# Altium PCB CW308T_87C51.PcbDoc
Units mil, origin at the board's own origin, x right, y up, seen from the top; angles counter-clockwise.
Board outline 2200.03 x 3300.03 mil, 2 copper layers (Top Layer, Bottom Layer); 35 components, 66 nets, 282 pads, 47 vias.
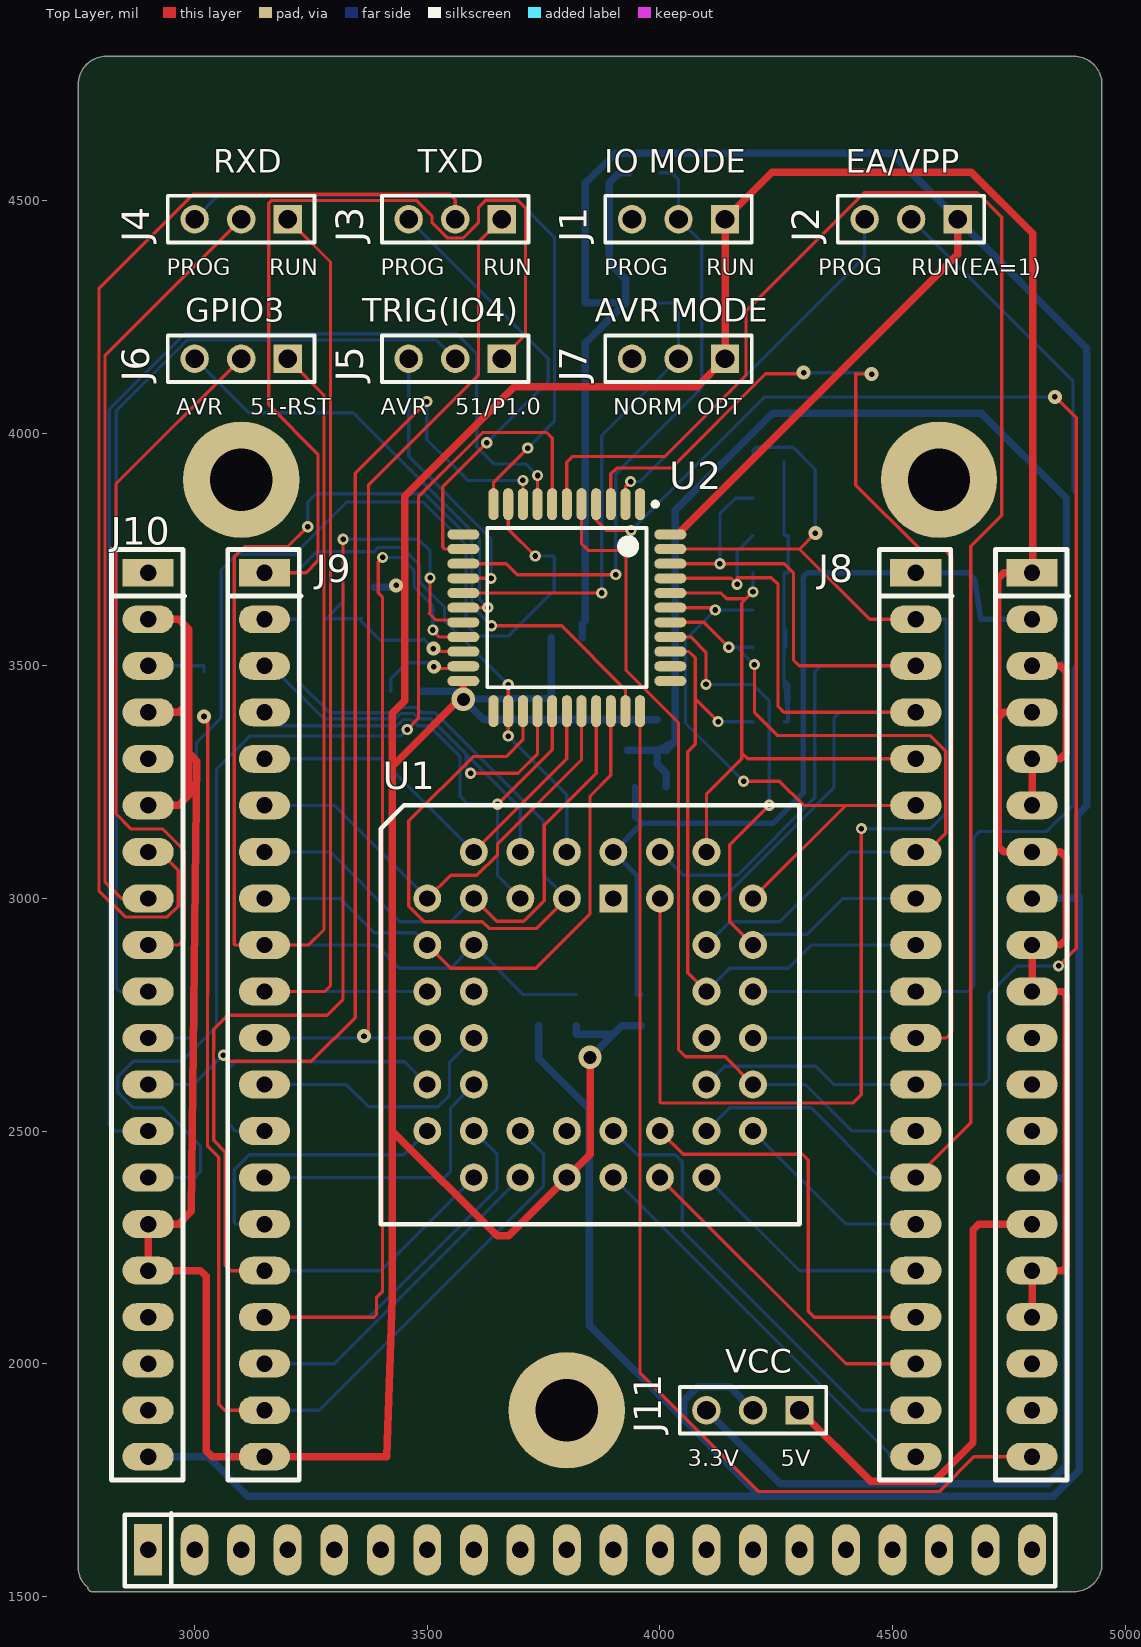
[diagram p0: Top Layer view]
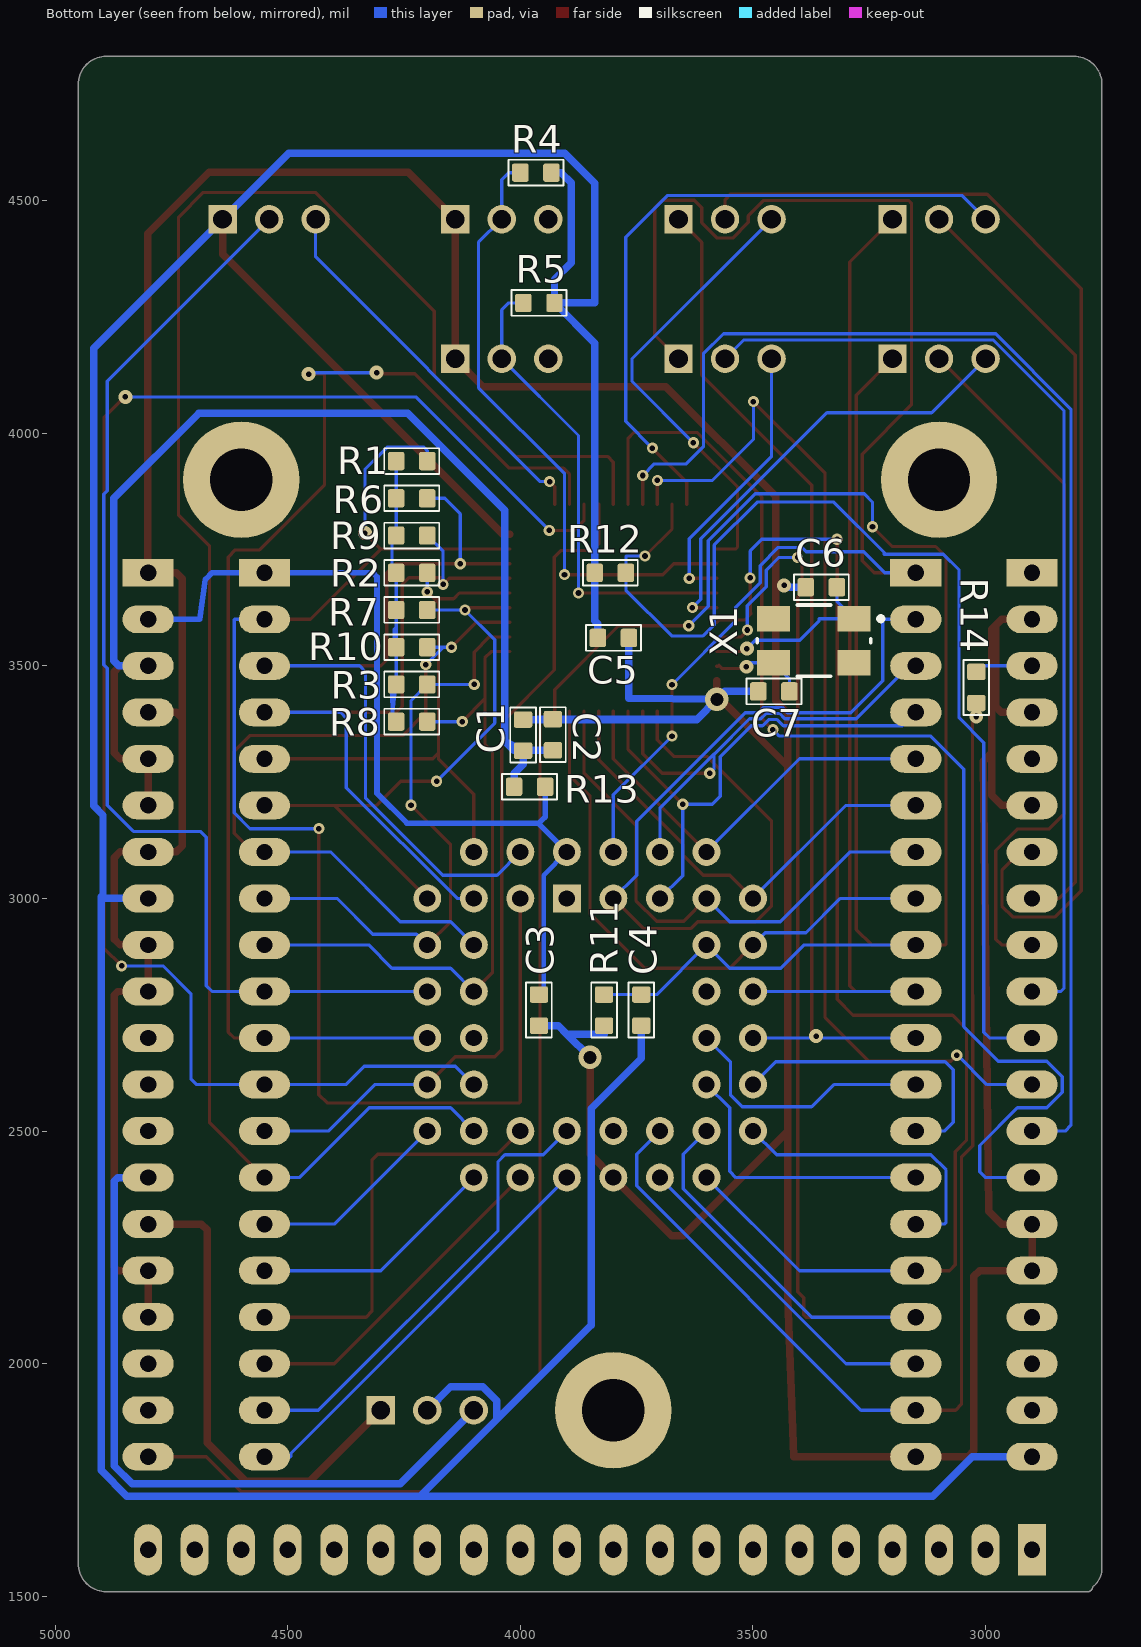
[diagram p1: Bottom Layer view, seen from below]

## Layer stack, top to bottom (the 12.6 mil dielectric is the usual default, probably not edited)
Top Solder: solder mask 0.4, Solder Resist, Dk 3.5
Top Layer: signal copper 1.4
Dielectric 1: dielectric 12.6, FR-4, Dk 4.8
Bottom Layer: signal copper 1.4
Bottom Solder: solder mask 0.4, Solder Resist, Dk 3.5

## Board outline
2769.99,1519.99 cw(c2800,1560) 2749.99,1560 2749.99,4750 cw(c2810,4750) 2810,4810.02 4890,4810.02 cw(c4890,4750) 4950.02,4750 4950.02,1570 cw(c4890,1570) 4890,1509.98 2780,1509.98 cw(c2780,1520)

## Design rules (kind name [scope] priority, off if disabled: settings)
BoardOutlineClearance [All] p1: gap=20 except(0: Arc-SplitContinuation Track-SplitContinuation SMDPad-SplitContinuation THPad-SplitContinuation Via-SplitContinuation Fill-SplitContinuation Poly-SplitContinuation Region-SplitContinuation Text-SplitContinuation)
Clearance Clearance_VCC [InNetClass('PWR')] p1: gap=10
Clearance Clearance_SENSITIVE [InNetClass('SENSITIVE')] p2: gap=15
Clearance Clearance_NORMAL [All] p3: gap=6
PolygonConnect [All] p1: connectstyle=Relief reliefconductorwidth=10 reliefentries=4 polygonreliefangle="90 Angle" airgapwidth=10
RoutingPriority RoutingPriority_SENSITIVE [InNetClass('SENSITIVE')] p1: routingpriority=10
RoutingPriority RoutingPriority_PWR [InNetClass('PWR')] p2: routingpriority=1
RoutingPriority RoutingPriority_ALL [All] p3: routingpriority=0
RoutingVias RoutingVias_PWR [InNetClass('PWR')] p1: holewidth=28 width=50 viastyle="Through Hole" minholewidth=26 minwidth=50 maxholewidth=28 maxwidth=50
RoutingVias [All] p2: holewidth=12 width=24 viastyle="Through Hole" minholewidth=12 minwidth=30 maxholewidth=28 maxwidth=50
SolderMaskExpansion [All] p1: expansion=4
Width Width_SENS [InNetClass('SENSITIVE')] p1: maxlimit=20 minlimit=10 preferedwidth=12 minimp=50.000000 maximp=50.000000 favimp=50.000000
Width WIDTH_PWR [InNetClass('PWR')] p2: maxlimit=100 minlimit=10 preferedwidth=16
Width [All] p3: maxlimit=100 minlimit=6 preferedwidth=7 minimp=50.000000 maximp=50.000000 favimp=50.000000
29 further rules are at their usual default settings.

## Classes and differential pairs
component class CW308T_87C51_CPU: C1 C2 C3 C4 C5 C6 C7 J1 J2 J3 J4 J5 J6 J7 J8 J9 R1 R2 R3 R4 R5 R6 R7 R8 R9 R10 R11 R12 R13 R14 U1 U2 X1
component class CW308T_87C51_CWCONN: J10 J11
net class SENSITIVE: SHUNTL
net class PWR: GND NetJ10_C14 NetJ10_C15 SHUNTH VCC
net class CLK: CLK NetJ9_19

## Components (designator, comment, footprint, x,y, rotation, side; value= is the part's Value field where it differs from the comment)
C1 "approved sub OK" CAPC1608X90N 3994,3351 r90 bottom
C2 "approved sub OK" CAPC1608X90N 3930,3352 r90 bottom
C3 "approved sub OK" CAPC1608X90N 3960,2760 r90 bottom
C4 "approved sub OK" CAPC1608X90N 3740,2760 r90 bottom
C5 "approved sub OK" CAPC1608X90N 3800,3560 r180 bottom
C6 "27p" CAPC1608X90N 3353,3669 r180 bottom
C7 "27p" CAPC1608X90N 3455,3445 r180 bottom
J1 "68000-203HLF" SMTC-TSW-103-07-X-S 4140,4460 r180 top
J2 "68000-203HLF" SMTC-TSW-103-07-X-S 4640,4460 r180 top
J3 "68000-203HLF" SMTC-TSW-103-07-X-S 3660,4460 r180 top
J4 "68000-203HLF" SMTC-TSW-103-07-X-S 3200,4460 r180 top
J5 "68000-203HLF" SMTC-TSW-103-07-X-S 3660,4160 r180 top
J6 "68000-203HLF" SMTC-TSW-103-07-X-S 3200,4160 r180 top
J7 "68000-203HLF" SMTC-TSW-103-07-X-S 4140,4160 r180 top
J8 "20-Pin Header" 801-87-020-10-001101 4550,3700 r0 top
J9 "20-Pin Header" 801-87-020-10-001101 3150,3700 r0 top
J10 "CW308_TARGETCON" CW308_TBOARD_CONN 2900,3700 r0 top locked
J11 "68000-203HLF" SMTC-TSW-103-07-X-S 4300,1900 r180 top
R1 "Thick Film" RESC1608X55N 4233.49,3940 r180 bottom
R2 "Thick Film" RESC1608X55N 4233.49,3700 r180 bottom
R3 "Thick Film" RESC1608X55N 4233.49,3460 r180 bottom
R4 "Thick Film" RESC1608X55N 3966.54,4560 r0 bottom
R5 "Thick Film" RESC1608X55N 3960,4280 r180 bottom
R6 "Thick Film" RESC1608X55N 4233.49,3860 r180 bottom
R7 "Thick Film" RESC1608X55N 4233.49,3620 r180 bottom
R8 "Thick Film" RESC1608X55N 4233.49,3380 r180 bottom
R9 "Thick Film" RESC1608X55N 4233.49,3780 r180 bottom
R10 "Thick Film" RESC1608X55N 4233.49,3540 r180 bottom
R11 "Thick Film" RESC1608X55N 3820,2760 r270 bottom
R12 "Thick Film" RESC1608X55N 3806.54,3700 r180 bottom
R13 "Thick Film" RESC1608X55N 3980,3240 r180 bottom
R14 "Thick Film" RESC1608X55N 3020,3453.46 r90 bottom
U1 "87C51" PLCC44_SOCKET 3500,3100 r0 top
U2 "ATmega8515-16AU" 44A_N 3800,3625 r270 top
X1 "ABMM2-8.000MHZ-E2-T" ABRA-ABMM2-4_V 3369,3554 r0 bottom

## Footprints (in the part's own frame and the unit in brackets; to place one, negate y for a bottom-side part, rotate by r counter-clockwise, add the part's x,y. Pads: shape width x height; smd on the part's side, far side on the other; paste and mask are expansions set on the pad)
44A_N [mm] "Thin QFP, 44-Leads, Body 10x10mm, Pitch 0.8mm, IPC Medium Density"
  oval 1.75x0.55 smd: 1(-5.65,4) 2(-5.65,3.2) 3(-5.65,2.4) 4(-5.65,1.6) 5(-5.65,0.8) 6(-5.65,0) 7(-5.65,-0.8) 8(-5.65,-1.6) 9(-5.65,-2.4) 10(-5.65,-3.2) 11(-5.65,-4) 23(5.65,-4) 24(5.65,-3.2) 25(5.65,-2.4) 26(5.65,-1.6) 27(5.65,-0.8) 28(5.65,0) 29(5.65,0.8) 30(5.65,1.6) 31(5.65,2.4) 32(5.65,3.2) 33(5.65,4)
  oval 0.55x1.75 smd: 12(-4,-5.65) 13(-3.2,-5.65) 14(-2.4,-5.65) 15(-1.6,-5.65) 16(-0.8,-5.65) 17(0,-5.65) 18(0.8,-5.65) 19(1.6,-5.65) 20(2.4,-5.65) 21(3.2,-5.65) 22(4,-5.65) 34(4,5.65) 35(3.2,5.65) 36(2.4,5.65) 37(1.6,5.65) 38(0.8,5.65) 39(0,5.65) 40(-0.8,5.65) 41(-1.6,5.65) 42(-2.4,5.65) 43(-3.2,5.65) 44(-4,5.65)
  silkscreen extent -5.77,-4.35 4.35,4.95, body extent -5,-5 5,5, height 1.2
801-87-020-10-001101 [mil]
  rect 110x60 hole 35: 1(0,0)
  oval 110x60 hole 35: 2(0,-100) 3(0,-200) 4(0,-300) 5(0,-400) 6(0,-500) 7(0,-600) 8(0,-700) 9(0,-800) 10(0,-900) 11(0,-1000) 12(0,-1100) 13(0,-1200) 14(0,-1300) 15(0,-1400) 16(0,-1500) 17(0,-1600) 18(0,-1700) 19(0,-1800) 20(0,-1900)
  silkscreen extent -79,-1950 79,50, body extent -50,-1950 50,50, height 224
ABRA-ABMM2-4_V [mm] "SMD, 4-Leads, Body 6.2x3.9mm, Pitch 4.4mm, Height 1.2mm"
  rect 1.8x1.4 smd: 1(-2.2,-1.2) 2(2.2,-1.2) 3(2.2,1.2) 4(-2.2,1.2)
  silkscreen extent -3.77,-1.95 3.1,1.95, body extent -3.1,-1.95 3.1,1.95, height 1.2
CAPC1608X90N [mm] "Chip Capacitor, Body 1.6x0.8mm, EIA 0603, IPC Medium Density"
  round 0.254 on Mech15: 0(0,0)
  rrect25% 0.9x1 smd: 1(-0.85,0) 2(0.85,0)
  Top Layer pour cut-out: -0.6,0.5 -0.4,0.7 0.4,0.7 0.6,0.5 0.6,-0.5 0.4,-0.7 -0.4,-0.7 -0.6,-0.5
  silkscreen extent -1.5,-0.7 1.5,0.7, body extent -0.85,-0.45 0.85,0.45, height 0.89
CW308_TBOARD_CONN [mil]
  rect 110x60 hole 35: A1(0,0) C1(1900,0)
  oval 110x60 hole 35: A2(0,-100) A3(0,-200) A4(0,-300) A5(0,-400) A6(0,-500) A7(0,-600) A8(0,-700) A9(0,-800) A10(0,-900) A11(0,-1000) A12(0,-1100) A13(0,-1200) A14(0,-1300) A15(0,-1400) A16(0,-1500) A17(0,-1600) A18(0,-1700) A19(0,-1800) A20(0,-1900) C2(1900,-100) C3(1900,-200) C4(1900,-300) C5(1900,-400) C6(1900,-500) C7(1900,-600) C8(1900,-700) C9(1900,-800) C10(1900,-900) C11(1900,-1000) C12(1900,-1100) C13(1900,-1200) C14(1900,-1300) C15(1900,-1400) C16(1900,-1500) C17(1900,-1600) C18(1900,-1700) C19(1900,-1800) C20(1900,-1900)
  rect 60x110 hole 35: B1(0,-2100)
  oval 60x110 hole 35: B2(100,-2100) B3(200,-2100) B4(300,-2100) B5(400,-2100) B6(500,-2100) B7(600,-2100) B8(700,-2100) B9(800,-2100) B10(900,-2100) B11(1000,-2100) B12(1100,-2100) B13(1200,-2100) B14(1300,-2100) B15(1400,-2100) B16(1500,-2100) B17(1600,-2100) B18(1700,-2100) B19(1800,-2100) B20(1900,-2100)
  round 250 hole 134: MH1(200,200) MH2(900,-1800) MH2(1700,200)
  silkscreen extent -79,-2179 1979,50, body extent -50,-2150 1950,50, height 224
PLCC44_SOCKET [mil]
  rect 60x60 hole 35: 1(400,-100)
  round 60 hole 35: 2(300,0) 3(300,-100) 4(200,0) 5(200,-100) 6(100,0) 7(0,-100) 8(100,-100) 9(0,-200) 10(100,-200) 11(0,-300) 12(100,-300) 13(0,-400) 14(100,-400) 15(0,-500) 16(100,-500) 17(0,-600) 18(100,-700) 19(100,-600) 20(200,-700) 21(200,-600) 22(300,-700) 23(300,-600) 24(400,-700) 25(400,-600) 26(500,-700) 27(500,-600) 28(600,-700) 29(700,-600) 30(600,-600) 31(700,-500) 32(600,-500) 33(700,-400) 34(600,-400) 35(700,-300) 36(600,-300) 37(700,-200) 38(600,-200) 39(700,-100) 40(600,0) 41(600,-100) 42(500,0) 43(500,-100) 44(400,0)
  silkscreen extent -100,-800 800,100, body extent -92,-792 792,92, height 302
RESC1608X55N [mm] "Chip Resistor, Body 1.6x0.8mm, EIA 0603, IPC Medium Density"
  round 0.254 on Mech15: 0(0,0)
  rrect25% 0.9x1 smd: 1(-0.85,0) 2(0.85,0)
  Top Layer pour cut-out: -0.6,0.5 -0.4,0.7 0.4,0.7 0.6,0.5 0.6,-0.5 0.4,-0.7 -0.4,-0.7 -0.6,-0.5
  silkscreen extent -1.5,-0.7 1.5,0.7, body extent -0.87,-0.47 0.88,0.48, height 0.54
SMTC-TSW-103-07-X-S [mm] ".025 SQ Post Terminal Strip Assembly, 1x3 Pins, Vertical, 2.54mm Pitch, Male"
  rect 1.55x1.55 hole 1.02: 1(0,0)
  round 1.55 hole 1.02: 2(2.54,0) 3(5.08,0)
  silkscreen extent -1.46,-1.27 6.54,1.27, body extent -1.27,-1.27 6.35,1.27, height 8.38

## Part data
C1 C2 C3 C4 C5: library part CAPC_100n_0603_X7R_50V_10%, "Capacitor SMD Cer 100nF 10% 50V X7R 0603"
C6 C7: library part CAPC_27p_0603_NP0_100V_1%, "Capacitor SMD Cer 27pF 1% 100V NP0 0603"
J1 J2 J3 J4 J5 J6 J7 J11: library part CMP-1024-00333-1
J8 J9: library part 801-87-020-10-001101, "1x20 Header, Machined"
J10: library part CW308_TBOARD, "CW308 \"Standard\" Target Board Connector"
R1 R2 R3 R4 R5 R6 R7 R8 R9 R10 R11 R12: library part RES_10K_0603_1%, "Resistor SMD chip 10k Ohm 0.1W 1% 0603"
R13 R14: library part RES_51R_0603_1%, "Resistor SMD chip 51 Ohm 0.1W 1% 0603"
U2: library part CMP-0095-00300-2, "8-bit AVR Microcontroller, 8KB Flash, 512 Bytes EEPROM, 512 Bytes SRAM, 4.5-5.5V, 44-pin TQFP, Industrial Grade (-40°C to 85°C)"
X1: library part CMP-0277-00003-1, "Ceramic Surface Mount Low Profile Quartz Crystal, 8 MHz, -20 to 70 degC, 4-Pin 6 x 3.6 x 1.2 mm SMD, RoHS, 1000pcs / Reel"

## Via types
v1: diameter 24, hole 12, Top Layer to Bottom Layer, tented both sides, 36 vias
v2: diameter 30, hole 12, Top Layer to Bottom Layer, tented both sides, 9 vias
v3: diameter 50, hole 28, Top Layer to Bottom Layer, 2 vias

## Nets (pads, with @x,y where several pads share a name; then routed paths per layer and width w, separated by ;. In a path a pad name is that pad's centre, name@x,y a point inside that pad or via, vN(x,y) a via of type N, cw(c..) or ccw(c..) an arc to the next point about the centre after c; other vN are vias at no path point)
51_RESET: C4.2 J6.1 J9.9 R11.1 U1.10 U2.32 | length 4286.4
  Top Layer w7: J6.1 3278,4082 3278,2933 3245,2900 J9.9 3086.5,2900 3085.09,2901.41 3085.09,3734.09 3107.5,3756.5 3200.5,3756.5 v1(3243,3799) ; v1(3638,3586) 3789,3586 3925.98,3449.02 U2.32
  Bottom Layer w7: J9.9 3390,2900 3440,2850 3550,2850 U1.10 3706.54,2793.46 C4.2 R11.1 ; v1(3243,3799) 3243,3852 3261,3870 3495,3870 3596.25,3768.75 3596.25,3627.75 v1(3638,3586)
51_RX: J4.1 J9.10 U1.11 | length 2182.8
  Top Layer w7: J9.10 3279.5,2800 3292,2812.5 3292,4368 J4.1
  Bottom Layer w7: J9.10 U1.11
51_TX: J3.1 J9.11 U1.13 | length 2228.6
  Top Layer w7: v2(3364,2704) 3373.5,2713.5 3373.5,3888.5 3610,4125 3610,4410 J3.1
  Bottom Layer w7: J9.11 U1.13
ALE/PROG: J8.11 U1.33 U2.3 | length 2715.7
  Top Layer w7: U2.3 3894.49,3912.5 3906.99,3925 4024.01,3925 4227.01,4127.99 4306.99,4127.99 v2(4309,4130) ; v2(4455,4127) 4422,4127 4421,4128 4421,3888.5 4560.5,3749 4612.5,3749 4627.73,3733.77 4627.73,2712.73 4615,2700 J8.11
  Bottom Layer w7: U1.33 J8.11 ; v2(4309,4130) 4452,4130 v2(4455,4127)
AVR_EA: J2.3 U2.2 | length 837.2
  Top Layer w7: U2.2 3925.98,3884.98 v1(3937,3896)
  Bottom Layer w7: v1(3937,3896) 3957,3896 4440,4379 J2.3
AVR_GPIO3: J6.3 U2.17 | length 980.4
  Top Layer w7: U2.17 v1(3630.13,3625)
  Bottom Layer w7: J6.3 3116,4044 3341,4044 3612,3773 3612,3643.13 v1(3630.13,3625)
AVR_MODE1: J1.2 R4.2 U2.14 | length 1329.7
  Top Layer w7: U2.14 3670,3719.49 3693.49,3696 v1(3905,3696)
  Bottom Layer w7: v1(3905,3696) 3905,3913 4090,4098 4090,4410 J1.2 4040,4545 4025,4560 R4.2
AVR_MODE2: J7.2 R5.1 U2.16 | length 1027
  Top Layer w7: U2.16 v1(3875,3656.5)
  Bottom Layer w7: v1(3875,3656.5) 3875,3995 J7.2 4040,4265 4025,4280 R5.1
AVR_RST: J10.A11 R12.2 U2.10 | length 2413.2
  Top Layer w7: U2.10 3674.02,3794 v1(3732,3736.02)
  Bottom Layer w7: J10.A11 2991.5,2700 3004,2712.5 3004,3335 3057,3388 3057,3706 3090.65,3739.65 3218,3739.65 3218,3743.59 3326.41,3852 3491,3852 3583.25,3759.75 3583.25,3588.25 3607.2,3564.3 3674.91,3564.3 3773.07,3662.47 R12.2 3773.07,3735 3772.05,3736.02 v1(3732,3736.02)
AVR_RX: J4.3 U2.11 | length 1459.6
  Top Layer w7: U2.11 3642.52,3894.52 v1(3716,3968)
  Bottom Layer w7: J4.3 3051,4511 3683.55,4511 3773.28,4421.28 3773.28,4025.28 v1(3716,3968)
AVR_TRIG: J5.3 U2.15 | length 604.8
  Top Layer w7: U2.15 v1(3637,3687.99)
  Bottom Layer w7: J5.3 3460,3950 3637,3773 v1(3637,3687.99)
AVR_TX: J3.3 U2.13 | length 969
  Top Layer w7: U2.13 3537.5,3750.98 3533.26,3755.23 3533.26,3884.88 v1(3628,3979.63)
  Bottom Layer w7: J3.3 3760,4160 3760,4111.63 v1(3628,3979.63)
CLK: J10.A3 R14.2 | length 133.1
  Bottom Layer w7: J10.A3 3020,3500 R14.2
EA/VPP: J2.2 J8.10 U1.35 | length 2450.6
  Bottom Layer w7: U1.35 J8.10 4662.5,2800 4675,2812.5 4675,3131.5 4687.5,3144 4831.5,3144 4888,3200.5 4888,3494.59 4895.5,3502.09 4895.5,3868.91 4888,3876.41 4888,3995.59 4888,4112 J2.2
GND: C1.2 C2.2 C3.1 C5.2 C6.1 C7.1 J1.1 J7.1 J9.20 J10.A2 J10.A4 J10.A6 J10.A15 J10.A16 J10.C1 J10.C4 J10.C7 J10.C9 J10.C10 J10.C16 J10.C17 R11.2 U1.22 U2.22 | length 12493.2
  Top Layer w16: J10.A6 2965.5,3200 2986.99,3221.49 2986.99,3313.01 ; J10.A4 2966,3400 2978.5,3412.5 2978.5,3587 ; J10.A2 2965.5,3600 2978.5,3587 ; v3(3577.56,3428) v3@3577.56,3436.56 ; U2.22 v3@3577.56,3436.56 ; v3(3850,2658.54) 3850,2450 U1.22 3675,2275 3650,2275 3425,2500 ; 4726.72,3112.78 4726.72,3687.5 4739.22,3700 J10.C1 4801,3700 4801,4429.14 4669.14,4561 4241,4561 J1.1 J7.1 4080.15,4100.15 3687.15,4100.15 3451.17,3864.17 3451.17,3424.63 3425,3398.46 3425,3292 ; J10.C17 J10.C16 4865.5,2200 4873.28,2207.78 4873.28,2792.22 4865.5,2800 J10.C10 J10.C9 4860.5,2900 4873.23,2912.73 4873.23,3087.27 4860.5,3100 J10.C7 4739.5,3100 4726.77,3112.73 4726.77,3387.27 4739.5,3400 J10.C4 ; 2978.5,3587 2986.99,3578.51 2986.99,3313.01 ; 2986.99,3313.01 3004.95,3295.05 2992.79,2327.29 2965.5,2300 J10.A15 J10.A16 3012.5,2200 3025,2187.5 3025,1812.5 3037.5,1800 J9.20 3412.5,1800 3425,2141.11 3425,2500 ; 3425,2500 3425,3292 ; 3425,3292 3428,3289 3430,3289 v3@3577.56,3436.56
  Bottom Layer w16: C6.1 3429,3669 v2(3433,3673) ; C7.1 3560.56,3445 v3@3576.97,3428.59 ; C5.2 3766.54,3430 3577.56,3428.6 v3@3576.97,3428.59 ; R11.2 3820,2708.5 3899.96,2708.5 ; v3(3850,2658.54) 3899.96,2708.5 ; C3.1 3918,2726.54 3899.96,2708.5 ; v3@3576.97,3428.59 v3(3577.56,3428) 3620.1,3385.46 ; 3620.1,3385.46 C2.2 ; 3620.1,3385.46 3621.1,3384.46 C2.2@3930,3384.46 ; C2.2@3930,3384.46 C2.2 ; C2.2@3930,3384.46 C1.2 3961,3385.46 C2.2
GPIO3: J6.2 J10.A9 | length 1542.8
  Top Layer w7: J10.A9 2965.5,2900 2978,2912.5 2978,3103 2932,3149 2863.98,3149 2830.99,3181.99 2830.99,3890.99 J6.2
GPIO4: J5.2 J10.A10 | length 2120.8
  Bottom Layer w7: J10.A10 2838.5,2800 2831.43,2807.07 2831.43,4048.04 2983.69,4200.31 3519.69,4200.31 J5.2
LED1: J10.C18
LED2: J10.C19
LED3: J10.C20 U2.33 | length 2401.8
  Top Layer w7: U2.33 3957.48,1979.88 4212.31,1725.05 4600.05,1725.05 4675,1800 J10.C20
MISO: J10.A13 U2.8 | length 2920.5
  Top Layer w7: U2.8 v1(3737.01,3909)
  Bottom Layer w7: J10.A13 2829,2500 2816.5,2512.5 2816.5,4051.85 2978.33,4213.68 3563.33,4213.68 3606.46,4170.54 3606.46,3970.54 3643.01,3934 3712.01,3934 v1(3737.01,3909)
MOSI: J10.A14 U2.7 | length 2689.4
  Top Layer w7: v1(3457,3363) 3481,3387 3481,3863.03 3619.48,4001.52 3756.48,4001.52 3768.5,3989.5 U2.7
  Bottom Layer w7: J10.A14 3000,2400 3012.5,2412.5 3012.5,2468.95 2931.45,2550 2868.45,2550 2834.97,2583.47 2834.97,2616.47 2868.5,2650 2972.5,2650 3047,2724.5 3047,3278 3118,3349 3443,3349 v1(3457,3363)
NetC6_2: C6.2 U2.20 X1.1 | length 412.5
  Top Layer w7: v2(3513,3537) 3519.49,3530.51 U2.20
  Bottom Layer w7: C6.2 3319.54,3638.39 X1.1 3358.24,3601.24 3358.24,3595.76 3399,3555 3488,3555 3490,3557 3493,3557 v2(3513,3537)
NetC7_2: C7.2 U2.21 X1.3 | length 206.8
  Top Layer w7: v2(3514,3498) 3518,3494 3566,3494 3573,3501 3574.98,3499.02 U2.21
  Bottom Layer w7: C7.2 3421.54,3472.68 X1.3 3505.24,3506.76 v2(3514,3498)
NetJ8_15: J8.15 U1.29 | length 432.8
  Bottom Layer w7: U1.29 4400,2300 J8.15
NetJ8_16: J8.16 U1.28 | length 532.8
  Bottom Layer w7: U1.28 4300,2200 J8.16
NetJ9_12: J9.12 U1.14 | length 572.8
  Bottom Layer w7: J9.12 3326,2600 3374,2552 3523,2552 3548,2577 3548,2648 U1.14
NetJ9_13: J9.13 U1.15 | length 658.7
  Bottom Layer w7: J9.13 3088.5,2500 3069.75,2518.75 3069.75,2631.75 3087,2649 3451,2649 U1.15
NetJ9_14: J9.14 U1.16 | length 612.8
  Bottom Layer w7: J9.14 3536.5,2400 3550,2413.5 3550,2550 U1.16
NetJ9_15: J9.15 U1.17 | length 629.1
  Bottom Layer w7: J9.15 3088.5,2300 3084.96,2303.54 3084.96,2416.53 3117.43,2449 3449,2449 U1.17
NetJ9_18: J9.18 U1.20 | length 715.7
  Bottom Layer w7: J9.18 3300,2000 U1.20
NetJ9_19: J9.19 R14.1 U1.21 | length 2533.7
  Top Layer w7: v2(3020,3391) 3028,3383 3028,2793 3027.5,2792.5 3027.5,2468.5 3052,2444 3052,1912.5 3064.5,1900 J9.19
  Bottom Layer w7: J9.19 3268,1900 3750,2382 3750,2450 U1.21
NetJ10_C14: J10.C14 J11.3 | length 1543.4
  Bottom Layer w16: J11.3 4258.5,1741.5 4834.5,1741.5 4873.28,1780.28 4873.28,2392.22 4865.5,2400 J10.C14
NetJ10_C15: J10.C15 J11.1 | length 1060.4
  Top Layer w16: J11.1 4453,1747 4590,1747 4673,1830 4673,2287.5 4685.5,2300 J10.C15
NetR1_1: R1.1 R2.1 R3.1 R6.1 R7.1 R8.1 R9.1 R10.1 | length 828.1
  Bottom Layer w7: R8.1 R8.1@4276,3380 ; R3.1 R3.1@4266.95,3469.05 ; R1.1 R6.1 R9.1 4276,3780 4276,3700 R2.1 R7.1 4266.95,3583.05 ; R3.1@4266.95,3469.05 R8.1@4276,3380 ; R3.1@4266.95,3469.05 R10.1 ; R3.1@4266.95,3469.05 4277,3459 R8.1@4276,3380 ; R3.1@4266.95,3469.05 4267.86,3460.09 4275.91,3380.91 R8.1@4276,3380 ; R10.1 4271,3540 4271,3579 4266.95,3583.05 ; R10.1 4266.95,3583.05
P2.6: J8.14 U1.30 U2.6 | length 4041.6
  Top Layer w7: U2.6 3800,3937.5 3812.5,3950 4011,3950 4185,4124 4185,4262 4440.59,4517.59 4681.58,4517.59 4734.62,4464.55 4734.62,3823.62 4668,3757 4668,2518 J8.14
  Bottom Layer w7: U1.30 4150,2550 4325,2550 4475,2400 J8.14
P2.7: J8.13 U1.31 U2.5 | length 1880.2
  Top Layer w7: U2.5 3831.5,3762.5 3846,3748 3912.5,3748 3927,3733.5 3927,3491 4040,3378 4040,2675 4055,2660 4140,2660 U1.31
  Bottom Layer w7: U1.31 4313,2600 4413,2500 J8.13
P3.6: J9.16 U1.18 U2.18 | length 2847.5
  Top Layer w7: J9.16 3077.5,2200 3065,2212.5 3065,2456 3041,2480 3041,2653.59 3040.5,2654.09 3040.5,2671.91 3041,2672.41 3041,2719 3071,2749 3285,2749 3319,2783 v1(3319,3772) ; v1(3506,3689) 3506,3614.5 3504,3612.5 3518,3598.5 3572.56,3598.5 U2.18
  Bottom Layer w7: J9.16 3400,2200 U1.18 ; v1(3319,3772) 3481,3772 3506,3747 v1(3506,3689)
P3.7: J9.17 U1.19 U2.19 | length 2939.8
  Top Layer w7: J9.17 3385.5,2100 3390.71,2105.21 3390.71,2141.91 3403.5,2154.7 3403.5,3648.05 3394.5,3657.05 3394.5,3723.5 v1(3404,3733) ; v1(3512,3577) 3512,3575.01 3525,3562.01 U2.19
  Bottom Layer w7: J9.17 3374,2100 3650,2376 3650,2450 U1.19 ; v1(3404,3733) 3444,3733 3471.5,3705.5 3471.5,3669.5 3512,3629 v1(3512,3577)
PA0: J5.1 J9.1 U1.2 U2.24 | length 3057.5
  Top Layer w7: J9.1 3239.5,3700 3264.92,3725.42 3264.92,3955.08 3159.31,4060.69 3159.31,4493.96 3165.67,4500.33 3476.67,4500.33 3510,4467 3510,4453 3543.55,4419.45 3576.77,4419.45 3610,4452.69 3610,4484.69 3625.75,4500.43 3694.74,4500.43 3711,4484.18 3711,4211 J5.1 ; v1(3674.02,3348.98) U2.24 v1(3674.02,3459.59)
  Bottom Layer w7: J9.1 3217,3700 3262,3745 3385.59,3745 3395.09,3754.5 3445.5,3754.5 3484.5,3715.5 3484.5,3678.5 3537,3626 3537,3596.6 v1(3674.02,3459.59) ; v1(3674.02,3348.98) 3800,3223 U1.2
PA1: J9.2 U1.3 U2.25 | length 2001.9
  Top Layer w7: U2.25 3705.51,3341.13 3669.38,3305 3598.38,3305 3460.36,3166.97 3460.36,2983.23 3493.59,2950 3618.59,2950 3633.09,2935.5 3735.5,2935.5 U1.3
  Bottom Layer w7: J9.2 3221,3600 3221,3468 3290,3399 3425.83,3399 3437.33,3410.5 3476.67,3410.5 3488.17,3399 3517,3399 3750,3166 3750,3050 U1.3
PA2: J9.3 U1.4 U2.26 | length 1077.6
  Top Layer w7: v1(3593,3269) 3694.98,3269 3737.01,3311.03 U2.26
  Bottom Layer w7: J9.3 3164,3500 3278,3386 3431.21,3386 3442.71,3397.5 3471.29,3397.5 3482.79,3386 3507.47,3386 3583.5,3309.97 3583.5,3278.5 v1(3593,3269) ; 3584,3310 3700,3194 U1.4
PA3: J9.4 U1.5 U2.27 | length 1115.4
  Top Layer w7: v1(3651,3202.5) 3768.5,3320 U2.27
  Bottom Layer w7: J9.4 3179,3371 3434.59,3371 3448.09,3384.5 3465.91,3384.5 3479.41,3371 3504.08,3371 3570.5,3304.58 3570.5,3219.5 3587.5,3202.5 v1(3651,3202.5) 3651,3049 U1.5
PA4: J9.5 U1.6 U2.28 | length 918.2
  Top Layer w7: U1.6 3800,3300 U2.28
  Bottom Layer w7: J9.5 3400,3300 U1.6
PA5: J9.6 U1.7 U2.29 | length 1005.9
  Top Layer w7: U1.7 3550,3050 3606.74,3050 3651,3094.26 3651,3117.26 3831.5,3297.76 U2.29
  Bottom Layer w7: J9.6 3300,3200 U1.7
PA6: J9.7 U1.8 U2.30 | length 1176.3
  Top Layer w7: U1.8 3649,2951 3707,2951 3751.5,2995.5 3751.5,3157.57 3862.99,3269.06 U2.30
  Bottom Layer w7: J9.7 3291,3100 3441,2950 3550,2950 U1.8
PA7: J9.8 U1.9 U2.31 | length 1264.6
  Top Layer w7: U1.9 3550,2850 3733,2850 3850,2967 3850,3220.18 3894.49,3264.66 U2.31
  Bottom Layer w7: J9.8 3312,3000 3386,2926 3474,2926 U1.9
PA8: J8.20 U1.24 | length 902
  Bottom Layer w7: U1.24 4493,1807 4493,1801 4494,1800 J8.20
PA9: J8.19 U1.25 | length 985.2
  Bottom Layer w7: U1.25 3951,2449 4033,2449 4048,2434 4048,2286 4434,1900 J8.19
PA10: J8.18 U1.26 | length 715.7
  Top Layer w7: U1.26 4400,2000 J8.18
PA11: J8.17 U1.27 | length 906.1
  Top Layer w7: U1.27 4050,2450 4306.5,2450 4319,2437.5 4319,2112.5 4331.5,2100 J8.17
PD0: J8.2 R1.2 U1.43 U2.43 | length 3081.4
  Top Layer w7: U1.43 4000,2562.5 4002.12,2560.38 4415.12,2560.38 4433,2578.26 v1(4433,3150) ; U2.43 4300,3750.98 ; v2(4334,3785) 4300,3750.98 ; J8.2 4450.98,3600 4300,3750.98
  Bottom Layer w7: R1.2 4200.02,3962.5 4207.09,3969.57 4286.43,3969.57 4334,3922 v2(4334,3785) ; v1(4433,3150) 4581,3150 4615.04,3184.04 4615.04,3598.96 4614,3600 J8.2
PD1: J8.3 R6.2 U1.42 U2.42 | length 1836.4
  Top Layer w7: U2.42 v1(4129,3719.49) 4267.51,3719.49 4287,3700 4287,3512.5 4299.5,3500 J8.3
  Bottom Layer w7: U1.42 4050,3050 4167,3050 4333,3216 4333,3487.5 4345.5,3500 J8.3 ; v1(4129,3719.49) 4129,3826.5 4162.5,3860 R6.2
PD2: J8.4 R9.2 U1.41 U2.41 | length 1643.5
  Top Layer w7: U2.41 4153.01,3687.99 v1(4166,3675) 4166,3689.5 4239.5,3689.5 4254,3675 4254,3412.5 4266.5,3400 J8.4
  Bottom Layer w7: U1.41 4136,3000 4374,3238 4374,3387.5 4386.5,3400 J8.4 ; v1(4166,3675) 4166,3745.98 R9.2
PD3: J8.5 R2.2 U1.40 U2.40 | length 1222.3
  Top Layer w7: U2.40 4130.9,3656.5 4143.4,3644 4185.02,3644 ; U1.40 4100,3224 4176,3300 4176,3312.5 ; J8.5 4188.5,3300 4176,3312.5 ; 4176,3312.5 4176,3634.98 ; 4176,3634.98 v1(4200.02,3659) 4185.02,3644 ; 4176,3634.98 4185.02,3644
  Bottom Layer w7: v1(4200.02,3659) R2.2
PD4: J8.6 R7.2 U1.39 U2.39 | length 1541.3
  Top Layer w7: U2.39 4114,3625 v1(4119,3620) ; v1(4180,3252) 4257,3252 4309,3200 ; U1.39 4400,3200 ; 4309,3200 J8.6 4400,3200 ; 4309,3200 4400,3200
  Bottom Layer w7: v1(4180,3252) 4055,3377 4055,3556 v1(4119,3620) R7.2
PD5: J8.7 R10.2 U1.38 U2.38 | length 1592.3
  Top Layer w7: U2.38 4094.5,3593.5 v1(4148,3540) ; v1(4203.23,3502.5) 4203.23,3399.77 4253,3350 4581.31,3350 4614.66,3316.66 4614.66,3139.66 4575,3100 J8.7
  Bottom Layer w7: U1.38 4150,2950 4258,2950 4408,3100 J8.7 ; v1(4148,3540) 4165.73,3540 ; R10.2 4165.73,3540 ; v1(4203.23,3502.5) 4165.73,3540
PD6: J8.8 R3.2 U1.37 U2.37 | length 1282.4
  Top Layer w7: U2.37 4066.5,3562.01 4099,3529.51 v1(4099,3460) ; U1.37 4150,2950 4150,3115.27 v1(4235,3200.27)
  Bottom Layer w7: v1(4099,3460) R3.2 4235,3425.02 v1(4235,3200.27) ; U1.37 4223,2923 4317,2923 4394,3000 J8.8
PD7: J8.9 R8.2 U1.36 U2.36 | length 1435.1
  Top Layer w7: U2.36 4062.5,3530.51 4076,3517.01 4076,3429 ; U1.36 4060,2840 4060,3315 4076,3331 4076,3429 ; v1(4125,3380) 4076,3429
  Bottom Layer w7: U1.36 4150,2850 4276,2850 4326,2900 J8.9 ; v1(4125,3380) R8.2
PSEN: J8.12 U1.32 U2.4 | length 3409.4
  Top Layer w7: U2.4 3862.99,3812.5 3884.49,3791 v1(3938,3791) ; v2(4849,4078) 4850,4078 4895,4033 4895,2893 v1(4857,2855)
  Bottom Layer w7: v1(3938,3791) 4225,4078 v2(4849,4078) ; U1.32 4139.55,2639.55 4335.45,2639.55 4375,2600 J8.12 4695.5,2600 4708,2612.5 4708,2795 4768,2855 v1(4857,2855)
RX: J4.2 J10.A8 | length 1653.4
  Top Layer w7: J10.A8 2842,3000 2807.5,3034.5 2807.5,4167.5 J4.2
SCK: J10.A12 U2.9 | length 2278.8
  Top Layer w7: v1(3062,2663) 3075,2650 3251,2650 3345,2744 3345,3914 v1(3499,4068) ; U2.9 v1(3705.51,3898.51)
  Bottom Layer w7: J10.A12 2997,2600 3060,2663 v1(3062,2663) ; v1(3499,4068) 3499,3986.46 3586.95,3898.51 v1(3705.51,3898.51)
SHUNTH: C1.1 C2.1 J10.C3 J10.C5 J10.C6 R13.1 | length 2600.7
  Top Layer w16: J10.C6 J10.C5 4860.5,3300 4873.23,3312.73 4873.23,3487.27 4860.5,3500 J10.C3
  Bottom Layer w16: C2.1 C1.1@3994,3318.54 ; R13.1 4013.46,3269 3994,3288.46 C1.1 ; J10.C3 4863,3500 4874,3511 4874,3860 4690.75,4043.25 4242.06,4043.25 4033.24,3834.43 4033.24,3337.5 ; C1.1 3995.97,3318.54 4014.28,3318.54 4033.24,3337.5 ; C1.1 C1.1@3994,3318.54 ; C1.1@3994,3318.54 4033.24,3337.5
SHUNTL: C3.2 J8.1 J10.C2 R13.2 U1.44 | length 1923.9
  Bottom Layer w10: U1.44 3950,3050 3950,2793.46 C3.2
  Bottom Layer w12: U1.44 3962,3162 ; R13.2 3946.54,3175 3959.54,3162 3962,3162 ; J10.C2 4689.5,3600 4677,3685.5 4662.5,3700 J8.1 4317,3700 4308,3691 4308,3226 4244,3162 3962,3162
TX: J3.2 J10.A7 | length 2551.8
  Top Layer w7: J10.A7 2925,3100 2964.79,3060.21 2964.79,2983.69 2941.45,2960.36 2850.64,2960.36 2794.29,3016.71 2794.29,4310.94 2996.69,4513.34 3548.69,4513.34 3560,4502.02 J3.2
VCC: C4.1 C5.1 J2.1 J10.A20 J10.C8 J11.2 R4.1 R5.2 R12.1 U2.44 | length 10256.5
  Top Layer w16: U2.44 4038,3782.48 4640,4384.48 J2.1
  Bottom Layer w16: J10.A20 3029,1800 3113.6,1715.4 4215.61,1715.4 ; C4.1 3740,2656 3848,2548 3848,2083.02 4051,1880.02 ; C5.1 3833.46,3590 3840,3596.54 R12.1 3840,4193.46 R5.2 ; R4.1 3912.5,4560 3890.81,4538.31 3890.81,4366.19 3926.54,4330.46 R5.2 ; J11.2 4150,1950 4081,1950 4051,1920 4051,1880.02 ; J10.C8 4897,3000 ; 3904.5,4602 3840,4537.5 3840,4280 R5.2 ; 3904.5,4602 4498,4602 ; 3904.5,4602 4498,4602 ; 4051,1880.02 4215.61,1715.4 ; 4215.61,1715.4 4845.61,1715.4 4901,1770.79 4901,3004 4897,3000 ; 4498,4602 J2.1 4917,4183 4917,3199.09 4897,3179.09 4897,3000
pads on no net: C1.0 C2.0 C3.0 C4.0 C5.0 C6.0 C7.0 J1.3 J7.3 J10.A1 J10.A5 J10.A17 J10.A18 J10.A19 J10.B1 J10.B2 J10.B3 J10.B4 J10.B5 J10.B6 J10.B7 J10.B8 J10.B9 J10.B10 J10.B11 J10.B12 J10.B13 J10.B14 J10.B15 J10.B16 J10.B17 J10.B18 J10.B19 J10.B20 J10.C11 J10.C12 J10.C13 J10.MH1 J10.MH2 R1.0 R2.0 R3.0 R4.0 R5.0 R6.0 R7.0 R8.0 R9.0 R10.0 R11.0 R12.0 R13.0 R14.0 U1.1 U1.12 U1.23 U1.34 U2.1 U2.12 U2.23 U2.34 U2.35 X1.2 X1.4

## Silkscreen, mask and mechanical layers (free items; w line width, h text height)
Top Overlay:
  text "RXD" at 3040,4560 h50
  text "TXD" at 3480,4560 h50
  text "IO MODE" at 3880,4560 h50
  text "EA/VPP" at 4400,4560 h50
  text "PROG" at 2940,4340 h35
  text "RUN" at 3160,4340 h35
  text "PROG" at 3400,4340 h35
  text "RUN" at 3620,4340 h35
  text "PROG" at 3880,4340 h35
  text "RUN" at 4100,4340 h35
  text "PROG" at 4340,4340 h35
  text "RUN(EA=1)" at 4540,4340 h35
  text "GPIO3" at 2980,4240 h50
  text "TRIG(IO4)" at 3360,4240 h50
  text "AVR MODE" at 3860,4240 h50
  text "AVR" at 2960,4040 h35
  text "51-RST" at 3120,4040 h35
  text "AVR" at 3400,4040 h35
  text "51/P1.0" at 3560,4040 h35
  text "NORM" at 3900,4040 h35
  text "OPT" at 4080,4040 h35
  text "VCC" at 4140,1980 h50
  text "3.3V" at 4060,1780 h35
  text "5V" at 4260,1780 h35
Mechanical 3:
  the board outline again, w15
